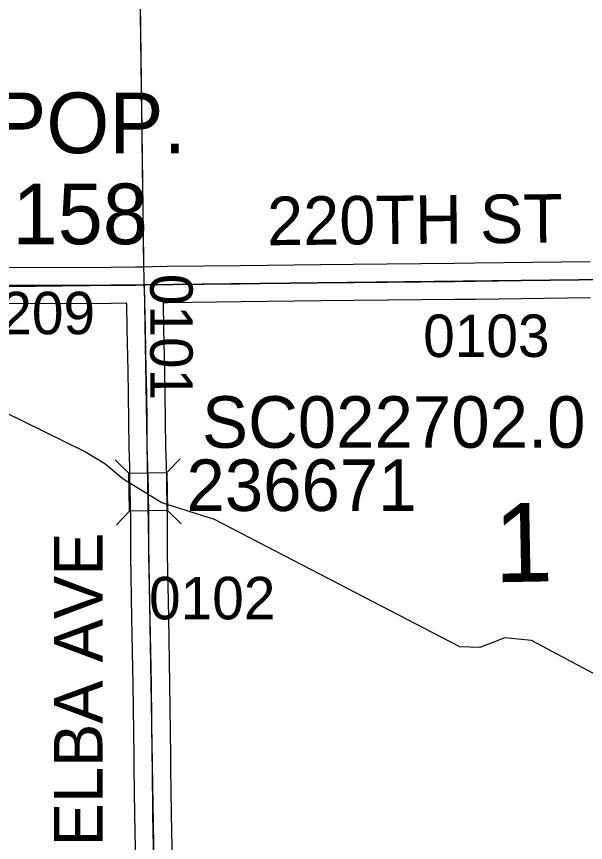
# Model space of a CAD drawing. Extents: x 23.6 to 68.7, y -63 to -29.
# Drawn here: x 37.481 to 38.418, y -46.611 to -45.249 of the extents above; entities that cross this region are included whole.
import ezdxf

# ---------------------------------------------------------------- set-up
doc = ezdxf.new("R2010")
doc.units = 0
for name, color, linetype in [('tdCoCorpPopTxt', 7, 'Continuous'), ('tdCoHydroRiver', 7, 'Continuous'), ('tdCoSecRdNmbr', 7, 'Continuous'), ('tdCoSecRdTxt', 7, 'Continuous'), ('tdCoSecRteBand', 7, 'Continuous'), ('tdCoSecRteCL', 7, 'Continuous'), ('tdCoSectLine', 7, 'Continuous'), ('tdCoSectLinePart', 7, 'Continuous'), ('tdCoSectNmbr', 7, 'Continuous'), ('tdCoStrucSec', 7, 'Continuous'), ('tdCoStrucSecCoName', 7, 'Continuous'), ('tdCoStrucSecFHWANum', 7, 'Continuous'), ('tdCoSurfAsphalt', 7, 'Continuous'), ('tdCoSurfGravel', 7, 'Continuous'), ('tdCoTwpBndryShd', 7, 'Continuous')]:
    doc.layers.add(name, color=color, linetype=linetype)

msp = doc.modelspace()

# ---------------------------------------------------------------- linework, layer by layer
at = {"layer": 'tdCoHydroRiver'}
for points in [[(38.2852, -46.2735), (38.2443, -46.2896), (38.2111, -46.2883), (37.8069, -46.0785), (37.7199, -46.0508), (37.6564, -46.0118), (37.6262, -45.9868), (37.5929, -45.9666), (37.3932, -45.8687), (37.3331, -45.8503), (37.2808, -45.8191), (37.2791, -45.8144)], [(38.9417, -46.6487), (38.9227, -46.6488), (38.8769, -46.6366), (38.8594, -46.6288), (38.7101, -46.51), (38.5958, -46.4289), (38.5244, -46.3821), (38.3294, -46.2779), (38.2852, -46.2735)]]:
    msp.add_lwpolyline(points, dxfattribs=at)
at = {"layer": 'tdCoSecRteBand'}
for points in [[(37.4491, -45.663), (37.6361, -45.6624), (37.677, -45.662), (37.6905, -45.6618), (37.7202, -45.6608), (37.7202, -45.6613), (37.7207, -45.6613), (37.7289, -45.6611), (37.729, -45.6611), (37.7291, -45.6611), (37.8496, -45.6599), (37.9819, -45.658), (37.982, -45.658), (37.9821, -45.658), (38.0363, -45.6576), (38.0363, -45.6576), (38.0363, -45.6576), (38.2027, -45.6561), (38.2361, -45.6557), (38.4258, -45.6531)], [(38.4266, -45.7131), (38.2369, -45.7157), (38.2369, -45.7157), (38.2368, -45.7157), (38.2033, -45.7161), (38.2032, -45.7161), (38.2032, -45.7161), (38.0369, -45.7176), (37.9827, -45.718), (37.8504, -45.7199), (37.8503, -45.7199), (37.8503, -45.7199), (37.7298, -45.7211), (37.7222, -45.7212), (37.7231, -45.7635), (37.7231, -45.7635), (37.7231, -45.7636), (37.7244, -45.8331), (37.7253, -45.8698), (37.7253, -45.87), (37.7253, -45.8702), (37.7258, -45.917), (37.7258, -45.9171), (37.7258, -45.9171), (37.7261, -45.958), (37.7272, -45.9896), (37.7272, -45.9899), (37.7272, -45.9902), (37.7276, -46.0095), (37.728, -46.024), (37.7281, -46.0243), (37.7281, -46.0245), (37.729, -46.0793), (37.729, -46.0795), (37.729, -46.0798), (37.729, -46.1369), (37.7309, -46.2403), (37.7309, -46.2403), (37.7309, -46.2403), (37.7329, -46.3497), (37.7329, -46.3498), (37.7329, -46.3498), (37.7344, -46.4673), (37.7347, -46.4865), (37.7347, -46.4866), (37.7347, -46.4867), (37.7355, -46.5643), (37.737, -46.6454)], [(37.6771, -46.6465), (37.6756, -46.5653), (37.6756, -46.5652), (37.6755, -46.5651), (37.6747, -46.4874), (37.6744, -46.4683), (37.6744, -46.4682), (37.6744, -46.4681), (37.6729, -46.3507), (37.6709, -46.2414), (37.669, -46.1377), (37.669, -46.1374), (37.669, -46.1371), (37.669, -46.08), (37.6681, -46.0258), (37.6676, -46.0112), (37.6676, -46.011), (37.6676, -46.0107), (37.6672, -45.9915), (37.6661, -45.9597), (37.6661, -45.9593), (37.6661, -45.9589), (37.6658, -45.9176), (37.6653, -45.871), (37.6644, -45.8343), (37.6644, -45.8343), (37.6644, -45.8342), (37.6631, -45.7647), (37.6622, -45.7223), (37.6618, -45.7223), (37.6617, -45.7221), (37.6365, -45.7223), (37.6364, -45.7223), (37.6364, -45.7223), (37.4496, -45.723)]]:
    msp.add_lwpolyline(points, dxfattribs=at)
at = {"layer": 'tdCoSecRteCL'}
for points in [[(37.6912, -45.6918), (37.7294, -45.6911), (37.85, -45.6899), (37.9823, -45.688), (38.0366, -45.6876), (38.203, -45.6861), (38.2365, -45.6857), (38.4262, -45.6831), (38.5678, -45.6815), (38.6153, -45.6811), (38.6952, -45.6802), (38.79, -45.6792), (38.8083, -45.679), (38.9694, -45.6783), (39.0023, -45.6779), (39.1762, -45.6765), (39.208, -45.6765), (39.3758, -45.6747), (39.5504, -45.6729), (39.5646, -45.6729), (39.6954, -45.6713), (39.7553, -45.6701), (39.9008, -45.6691)], [(37.6912, -45.6918), (37.6774, -45.692), (37.6363, -45.6923), (37.4492, -45.693)], [(37.7071, -46.646), (37.7055, -46.5648), (37.7047, -46.487), (37.7044, -46.4678), (37.7029, -46.3502), (37.7009, -46.2409), (37.699, -46.1371), (37.699, -46.0798), (37.6981, -46.025), (37.6976, -46.0102), (37.6972, -45.9907), (37.6961, -45.9586), (37.6958, -45.9174), (37.6953, -45.8705), (37.6944, -45.8337), (37.6931, -45.7641), (37.6921, -45.7197), (37.6915, -45.6997), (37.6912, -45.6918)]]:
    msp.add_lwpolyline(points, dxfattribs=at)
at = {"layer": 'tdCoSectLine'}
for points in [[(37.6909, -45.6918), (37.6777, -44.6808)], [(36.7012, -45.7036), (37.6909, -45.6918)], [(37.6909, -45.6918), (38.6948, -45.6802)], [(37.6909, -45.6918), (37.7067, -46.646)]]:
    msp.add_lwpolyline(points, dxfattribs=at)
at = {"layer": 'tdCoSectLinePart'}
msp.add_lwpolyline([(37.6905, -45.6619), (37.6785, -44.7428)], dxfattribs=at)
at = {"layer": 'tdCoStrucSec'}
for p, q in [((37.7286, -46.0011), (37.7504, -45.9786)), ((37.666, -46.0022), (37.6435, -45.9804)), ((37.6671, -46.0648), (37.6453, -46.0873)), ((37.7297, -46.0637), (37.7522, -46.0855))]:
    msp.add_line(p, q, dxfattribs=at)
msp.add_lwpolyline([(37.6671, -46.0648), (37.666, -46.0022), (37.7286, -46.0011), (37.7297, -46.0637)], close=True, dxfattribs=at)
at = {"layer": 'tdCoSurfAsphalt'}
msp.add_lwpolyline([(37.4492, -45.693), (37.6363, -45.6923), (37.6774, -45.692), (37.6912, -45.6918), (37.7294, -45.6911), (37.85, -45.6899), (37.9823, -45.688), (38.0366, -45.6876), (38.203, -45.6861), (38.2365, -45.6857), (38.4262, -45.6831)], dxfattribs=at)
at = {"layer": 'tdCoSurfGravel'}
msp.add_lwpolyline([(37.7071, -46.646), (37.7055, -46.5648), (37.7047, -46.487), (37.7044, -46.4678), (37.7029, -46.3502), (37.7009, -46.2409), (37.699, -46.1371), (37.699, -46.0798), (37.6981, -46.025), (37.6976, -46.0102), (37.6972, -45.9907), (37.6961, -45.9586), (37.6958, -45.9174), (37.6953, -45.8705), (37.6944, -45.8337), (37.6931, -45.7641), (37.6921, -45.7197), (37.6915, -45.6997), (37.6912, -45.6918)], dxfattribs=at)
at = {"layer": 'tdCoTwpBndryShd'}
msp.add_lwpolyline([(44.659, -45.6063), (43.6569, -45.6219), (42.6564, -45.6349), (41.6548, -45.649), (40.661, -45.6604), (39.6539, -45.6718), (38.6948, -45.6802), (37.6909, -45.6918), (36.7012, -45.7036), (36.6871, -45.7039), (35.6948, -45.7141), (35.6828, -45.7143), (34.6942, -45.7256), (34.6845, -45.726), (33.6895, -45.7373), (33.6806, -45.7374), (32.7232, -45.7449)], dxfattribs=at)

# ---------------------------------------------------------------- texts
at = {"layer": 'tdCoCorpPopTxt'}
for s, p in [('POP.', (37.4405, -45.4747)), ('158', (37.4742, -45.6247))]:
    msp.add_text(s, height=0.1, dxfattribs=at).set_placement(p)
at = {"layer": 'tdCoSecRdNmbr'}
for s, rotation, p in [('0101', 270.0274, (37.7009, -45.6735)), ('0209', 0.0294, (37.4019, -45.7732)), ('0103', 0.03, (38.1509, -45.8107)), ('0102', 0.0296, (37.6991, -46.2431))]:
    msp.add_text(s, height=0.07, rotation=rotation, dxfattribs=at).set_placement(p)
at = {"layer": 'tdCoSecRdTxt'}
for s, rotation, p in [('220TH ST', 0.5291, (37.8939, -45.6265)), ('ELBA AVE', 90, (37.6224, -46.6173))]:
    msp.add_text(s, height=0.08, rotation=rotation, dxfattribs=at).set_placement(p)
at = {"layer": 'tdCoSectNmbr'}
msp.add_text('1', height=0.13, rotation=1.03, dxfattribs=at).set_placement((38.2688, -46.1821))
at = {"layer": 'tdCoStrucSecCoName'}
msp.add_text('SC022702.0', height=0.085, dxfattribs=at).set_placement((37.7864, -45.9603))
at = {"layer": 'tdCoStrucSecFHWANum'}
msp.add_text('236671', height=0.085, dxfattribs=at).set_placement((37.7607, -46.0645))

doc.saveas('drawing.dxf')
